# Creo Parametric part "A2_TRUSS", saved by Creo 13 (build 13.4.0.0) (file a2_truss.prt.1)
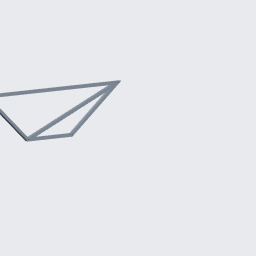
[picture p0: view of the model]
Units: millimeter Newton Second (mmNs); MM, TONNE, SECS
Materials in the file: STEEL_HSLA

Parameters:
  PTC_MATERIAL_NAME = "STEEL_HSLA"
  GRANTA_DATALINK_VERSION = "5"
  GRANTA_DATABASE_KEY = "Granta_Typical_Materials"
  GRANTA_IDENTITY_GUID = "38365331-f8c4-4cb8-a340-8972007108b5"
  GRANTA_VERSION_GUID = "ca78ab58-b03d-45f7-bd0e-e1c5c029d945"
  GRANTA_MODEL_REFERENCE = "00000000-0000-0000-0000-000000000000"

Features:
  1. datum plane "RIGHT"
  2. datum plane "TOP"
  3. datum plane "FRONT"
  4. coordinate system
  5. curve
  6. protrusion
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
Surfaces: 20 plane, 4 cylinder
